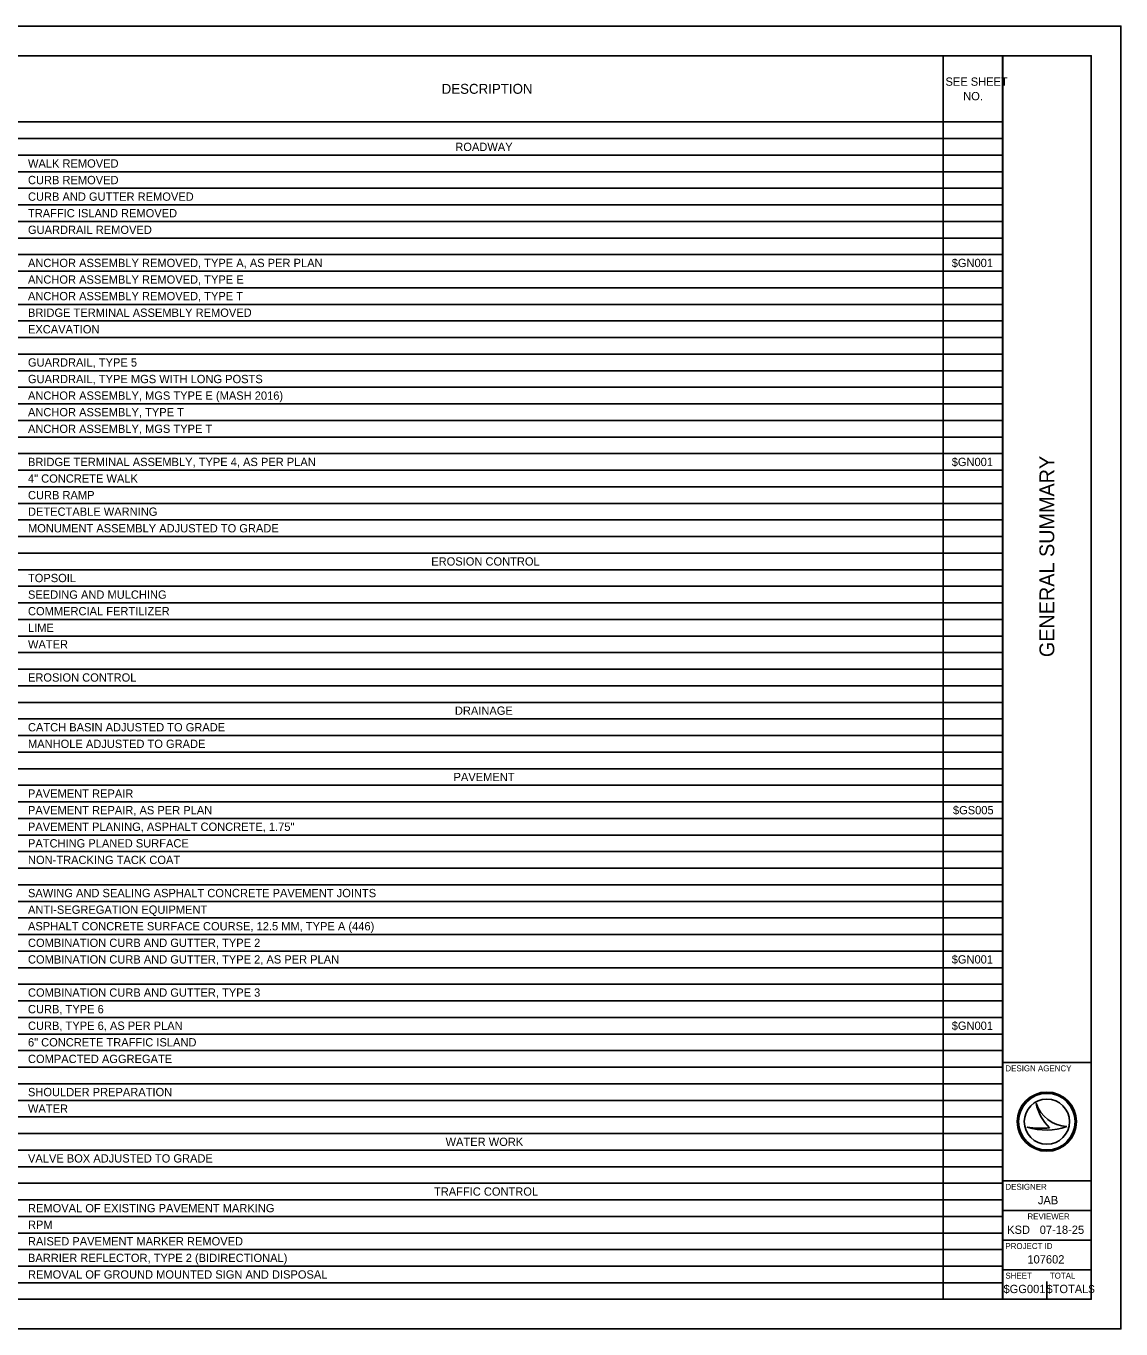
# Model space of a CAD drawing. Extents: x 0 to 34, y 0 to 22.
# Drawn here: x 15.52 to 34, y 0 to 22 of the extents above; entities that cross this region are included whole.
import ezdxf

# ---------------------------------------------------------------- set-up
doc = ezdxf.new("R2010")
doc.units = 0
for name, color, linetype in [('Default', 7, 'Continuous'), ('SH_Border', 7, 'Continuous'), ('SH_Cut_Line', 7, 'Continuous'), ('SH_Data', 7, 'Continuous')]:
    doc.layers.add(name, color=color, linetype=linetype)

msp = doc.modelspace()

# ---------------------------------------------------------------- linework, layer by layer
at = {"layer": 'Default'}
for p, q in [((1.5, 21.5), (32.004, 21.5)), ((30.999, 21.5), (30.999, 0.5)), ((32.004, 21.5), (32.004, 0.5)), ((1.5, 20.38), (32.004, 20.38)), ((1.5, 20.1), (32.004, 20.1)), ((1.5, 19.82), (32.004, 19.82)), ((1.5, 19.54), (32.004, 19.54)), ((1.5, 19.26), (32.004, 19.26)), ((1.5, 18.98), (32.004, 18.98)), ((1.5, 18.7), (32.004, 18.7)), ((1.5, 18.42), (32.004, 18.42)), ((1.5, 18.14), (32.004, 18.14)), ((1.5, 17.86), (32.004, 17.86)), ((1.5, 17.58), (32.004, 17.58)), ((1.5, 17.3), (32.004, 17.3)), ((1.5, 17.02), (32.004, 17.02)), ((1.5, 16.74), (32.004, 16.74)), ((1.5, 16.46), (32.004, 16.46)), ((1.5, 16.18), (32.004, 16.18)), ((1.5, 15.9), (32.004, 15.9)), ((1.5, 15.62), (32.004, 15.62)), ((1.5, 15.34), (32.004, 15.34)), ((1.5, 15.06), (32.004, 15.06)), ((1.5, 14.78), (32.004, 14.78)), ((1.5, 14.5), (32.004, 14.5)), ((1.5, 14.22), (32.004, 14.22)), ((1.5, 13.94), (32.004, 13.94)), ((1.5, 13.66), (32.004, 13.66)), ((1.5, 13.38), (32.004, 13.38)), ((1.5, 13.1), (32.004, 13.1)), ((1.5, 12.82), (32.004, 12.82)), ((1.5, 12.54), (32.004, 12.54)), ((1.5, 12.26), (32.004, 12.26)), ((1.5, 11.98), (32.004, 11.98)), ((1.5, 11.7), (32.004, 11.7)), ((1.5, 11.42), (32.004, 11.42)), ((1.5, 11.14), (32.004, 11.14)), ((1.5, 10.86), (32.004, 10.86)), ((1.5, 10.58), (32.004, 10.58)), ((1.5, 10.3), (32.004, 10.3)), ((1.5, 10.02), (32.004, 10.02)), ((1.5, 9.74), (32.004, 9.74)), ((1.5, 9.46), (32.004, 9.46)), ((1.5, 9.18), (32.004, 9.18)), ((1.5, 8.9), (32.004, 8.9)), ((1.5, 8.62), (32.004, 8.62)), ((1.5, 8.34), (32.004, 8.34)), ((1.5, 8.06), (32.004, 8.06)), ((1.5, 7.78), (32.004, 7.78)), ((1.5, 7.5), (32.004, 7.5)), ((1.5, 7.22), (32.004, 7.22)), ((1.5, 6.94), (32.004, 6.94)), ((1.5, 6.66), (32.004, 6.66)), ((1.5, 6.38), (32.004, 6.38)), ((1.5, 6.1), (32.004, 6.1)), ((1.5, 5.82), (32.004, 5.82)), ((1.5, 5.54), (32.004, 5.54)), ((1.5, 5.26), (32.004, 5.26)), ((1.5, 4.98), (32.004, 4.98)), ((1.5, 4.7), (32.004, 4.7)), ((1.5, 4.42), (32.004, 4.42)), ((1.5, 4.14), (32.004, 4.14)), ((1.5, 3.86), (32.004, 3.86)), ((1.5, 3.58), (32.004, 3.58)), ((1.5, 3.3), (32.004, 3.3)), ((1.5, 3.02), (32.004, 3.02)), ((1.5, 2.74), (32.004, 2.74)), ((1.5, 2.46), (32.004, 2.46)), ((1.5, 2.18), (32.004, 2.18)), ((1.5, 1.9), (32.004, 1.9)), ((1.5, 1.62), (32.004, 1.62)), ((1.5, 1.34), (32.004, 1.34)), ((1.5, 1.06), (32.004, 1.06)), ((1.5, 0.78), (32.004, 0.78)), ((1.5, 0.5), (32.004, 0.5))]:
    msp.add_line(p, q, dxfattribs=at)
at = {"layer": 'SH_Border'}
for p, q in [((32, 0.5), (32, 21.5)), ((32, 4.5), (33.5, 4.5)), ((32, 2.5), (33.5, 2.5)), ((32, 2), (33.5, 2)), ((32, 1.5), (33.5, 1.5)), ((32, 1), (33.5, 1))]:
    msp.add_line(p, q, dxfattribs=at)
msp.add_lwpolyline([(1.5, 21.5), (33.5, 21.5), (33.5, 0.5), (1.5, 0.5)], close=True, dxfattribs=at)
at = {"layer": 'SH_Cut_Line'}
msp.add_lwpolyline([(0, 0), (34, 0), (34, 22), (0, 22)], close=True, dxfattribs=at)
at = {"layer": 'SH_Data'}
for p, q in [((32.567, 3.81), (32.567, 3.81)), ((32.417, 3.41), (32.417, 3.41)), ((32.75, 3.5), (32.75, 3.5)), ((33.087, 3.419), (33.087, 3.419)), ((32.375, 0.675), (32.375, 0.675)), ((32.75, 0.5), (32.75, 0.8))]:
    msp.add_line(p, q, dxfattribs=at)
for radius in [0.5, 0.477, 0.477, 0.382]:
    msp.add_circle((32.75, 3.5), radius, dxfattribs=at)
for centre, radius, start, end in [((33.116, 3.998), 0.58, 198.9257, 198.9319), ((33.347, 3.97), 0.796, 191.6379, 191.6421), ((33.116, 3.998), 0.58, 198.9319, 267.1657), ((33.347, 3.97), 0.796, 191.6421, 226.0947), ((32.739, 4.37), 1.013, 251.4576, 290.0832), ((32.648, 4.654), 1.266, 259.4964, 259.4995), ((32.739, 4.37), 1.013, 251.4527, 251.4576), ((32.648, 4.654), 1.266, 259.4995, 276.6672)]:
    msp.add_arc(centre, radius, start, end, dxfattribs=at)

# ---------------------------------------------------------------- texts
at = {"layer": 'Default'}
for s, height, p in [('SEE SHEET ', 0.14, (31.038, 20.992)), ('DESCRIPTION', 0.168, (22.532, 20.856)), ('NO.', 0.14, (31.337, 20.747)), ('ROADWAY', 0.14, (22.763, 19.89)), ('WALK REMOVED', 0.14, (15.549, 19.61)), ('CURB REMOVED', 0.14, (15.549, 19.33)), ('CURB AND GUTTER REMOVED', 0.14, (15.549, 19.05)), ('TRAFFIC ISLAND REMOVED', 0.14, (15.549, 18.77)), ('GUARDRAIL REMOVED', 0.14, (15.549, 18.49)), ('ANCHOR ASSEMBLY REMOVED, TYPE A, AS PER PLAN', 0.14, (15.549, 17.93)), ('$GN001', 0.14, (31.143, 17.93)), ('ANCHOR ASSEMBLY REMOVED, TYPE E', 0.14, (15.549, 17.65)), ('ANCHOR ASSEMBLY REMOVED, TYPE T', 0.14, (15.549, 17.37)), ('BRIDGE TERMINAL ASSEMBLY REMOVED', 0.14, (15.549, 17.09)), ('EXCAVATION', 0.14, (15.549, 16.81)), ('GUARDRAIL, TYPE 5', 0.14, (15.549, 16.25)), ('GUARDRAIL, TYPE MGS WITH LONG POSTS', 0.14, (15.549, 15.97)), ('ANCHOR ASSEMBLY, MGS TYPE E (MASH 2016)', 0.14, (15.549, 15.69)), ('ANCHOR ASSEMBLY, TYPE T', 0.14, (15.549, 15.41)), ('ANCHOR ASSEMBLY, MGS TYPE T', 0.14, (15.549, 15.13)), ('BRIDGE TERMINAL ASSEMBLY, TYPE 4, AS PER PLAN', 0.14, (15.549, 14.57)), ('$GN001', 0.14, (31.143, 14.57)), ('4" CONCRETE WALK', 0.14, (15.549, 14.29)), ('CURB RAMP', 0.14, (15.549, 14.01)), ('DETECTABLE WARNING', 0.14, (15.549, 13.73)), ('MONUMENT ASSEMBLY ADJUSTED TO GRADE', 0.14, (15.549, 13.45)), ('EROSION CONTROL', 0.14, (22.357, 12.89)), ('TOPSOIL', 0.14, (15.549, 12.61)), ('SEEDING AND MULCHING', 0.14, (15.549, 12.33)), ('COMMERCIAL FERTILIZER', 0.14, (15.549, 12.05)), ('LIME', 0.14, (15.549, 11.77)), ('WATER', 0.14, (15.549, 11.49)), ('EROSION CONTROL', 0.14, (15.549, 10.93)), ('DRAINAGE', 0.14, (22.756, 10.37)), ('CATCH BASIN ADJUSTED TO GRADE', 0.14, (15.549, 10.09)), ('MANHOLE ADJUSTED TO GRADE', 0.14, (15.549, 9.81)), ('PAVEMENT', 0.14, (22.733, 9.25)), ('PAVEMENT REPAIR', 0.14, (15.549, 8.97)), ('PAVEMENT REPAIR, AS PER PLAN', 0.14, (15.549, 8.69)), ('$GS005', 0.14, (31.164, 8.69)), ('PAVEMENT PLANING, ASPHALT CONCRETE, 1.75"', 0.14, (15.549, 8.41)), ('PATCHING PLANED SURFACE', 0.14, (15.549, 8.13)), ('NON-TRACKING TACK COAT', 0.14, (15.549, 7.85)), ('SAWING AND SEALING ASPHALT CONCRETE PAVEMENT JOINTS', 0.14, (15.549, 7.29)), ('ANTI-SEGREGATION EQUIPMENT', 0.14, (15.549, 7.01)), ('ASPHALT CONCRETE SURFACE COURSE, 12.5 MM, TYPE A (446)', 0.14, (15.549, 6.73)), ('COMBINATION CURB AND GUTTER, TYPE 2', 0.14, (15.549, 6.45)), ('COMBINATION CURB AND GUTTER, TYPE 2, AS PER PLAN', 0.14, (15.549, 6.17)), ('$GN001', 0.14, (31.143, 6.17)), ('COMBINATION CURB AND GUTTER, TYPE 3', 0.14, (15.549, 5.61)), ('CURB, TYPE 6', 0.14, (15.549, 5.33)), ('CURB, TYPE 6, AS PER PLAN', 0.14, (15.549, 5.05)), ('$GN001', 0.14, (31.143, 5.05)), ('6" CONCRETE TRAFFIC ISLAND', 0.14, (15.549, 4.77)), ('COMPACTED AGGREGATE', 0.14, (15.549, 4.49)), ('SHOULDER PREPARATION', 0.14, (15.549, 3.93)), ('WATER', 0.14, (15.549, 3.65)), ('WATER WORK', 0.14, (22.599, 3.09)), ('VALVE BOX ADJUSTED TO GRADE', 0.14, (15.549, 2.81)), ('TRAFFIC CONTROL', 0.14, (22.403, 2.25)), ('REMOVAL OF EXISTING PAVEMENT MARKING', 0.14, (15.549, 1.97)), ('RPM', 0.14, (15.549, 1.69)), ('RAISED PAVEMENT MARKER REMOVED', 0.14, (15.549, 1.41)), ('BARRIER REFLECTOR, TYPE 2 (BIDIRECTIONAL)', 0.14, (15.549, 1.13)), ('REMOVAL OF GROUND MOUNTED SIGN AND DISPOSAL', 0.14, (15.549, 0.85))]:
    msp.add_text(s, height=height, dxfattribs=at).set_placement(p)
at = {"layer": 'SH_Data'}
msp.add_text('GENERAL SUMMARY', height=0.25, rotation=90, dxfattribs=at).set_placement((32.875, 11.344))
for s, height, p in [('DESIGN AGENCY', 0.1, (32.05, 4.35)), ('DESIGNER', 0.1, (32.05, 2.35)), ('JAB', 0.14, (32.598, 2.105)), ('REVIEWER', 0.1, (32.422, 1.85)), ('KSD', 0.14, (32.08, 1.605)), ('07-18-25', 0.14, (32.629, 1.605)), ('PROJECT ID', 0.1, (32.05, 1.35)), ('107602', 0.14, (32.421, 1.105)), ('SHEET', 0.1, (32.05, 0.85)), ('TOTAL', 0.1, (32.8, 0.85)), ('$GG001', 0.14, (32.018, 0.605)), ('$TOTAL$', 0.14, (32.743, 0.605))]:
    msp.add_text(s, height=height, dxfattribs=at).set_placement(p)

doc.saveas('drawing.dxf')
